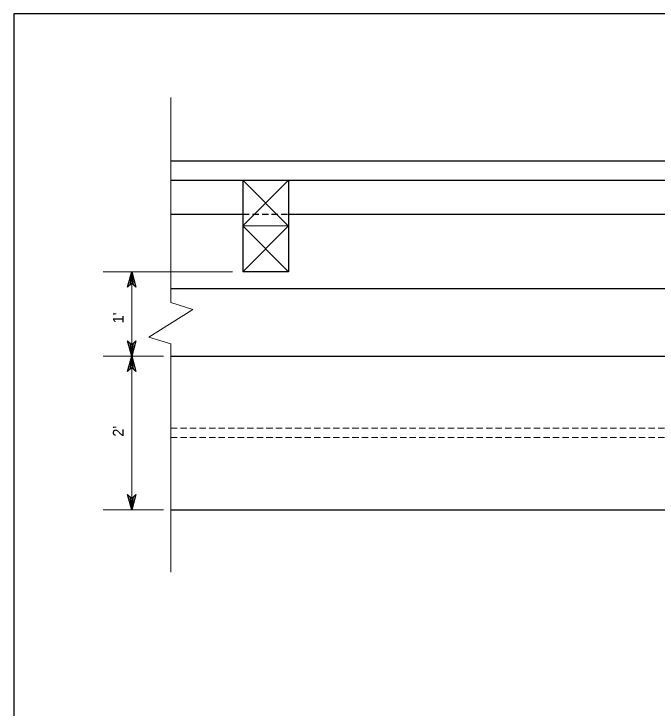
# Model space of a CAD drawing. Extents: x 993470 to 994006, y 1010815 to 1011161.
# Drawn here: x 993470 to 993630.6, y 1010988.2 to 1011161.5 of the extents above; entities that cross this region are included whole.
import ezdxf
from ezdxf.enums import TextEntityAlignment as Align

# ---------------------------------------------------------------- set-up
doc = ezdxf.new("R2010")
doc.units = 0
doc.header["$LTSCALE"] = 0.53
doc.linetypes.add('LONG_DASHED', pattern=[7.5, 6, -1.5])
doc.linetypes.add('MEDIUM_DASHED', pattern=[4.5, 3, -1.5])
for name, color, linetype, lineweight in [('1', 7, 'Continuous', 25), ('15', 7, 'Continuous', 13), ('16', 7, 'Continuous', 25), ('20', 7, 'Continuous', 13), ('30', 7, 'Continuous', 25), ('32', 7, 'Continuous', 25)]:
    doc.layers.add(name, color=color, linetype=linetype, lineweight=lineweight)

msp = doc.modelspace()

# ---------------------------------------------------------------- linework, layer by layer
at = {"layer": '1'}
for p, q in [((993527.157, 1011119.934), (993527.157, 1011097.116)), ((993538.559, 1011119.934), (993538.559, 1011097.116)), ((993509.149, 1011076.054), (993918.64, 1011076.054))]:
    msp.add_line(p, q, dxfattribs=at)
at = {"layer": '1', "linetype": 'MEDIUM_DASHED', "lineweight": 13}
for p, q in [((993509.149, 1011058.023), (993707.785, 1011058.023)), ((993509.149, 1011055.697), (993707.785, 1011055.697))]:
    msp.add_line(p, q, dxfattribs=at)
at = {"layer": '15'}
msp.add_lwpolyline([(993509.149, 1011079.129), (993503.685, 1011080.805), (993514.613, 1011087.717), (993509.149, 1011089.393)], dxfattribs=at)
at = {"layer": '16'}
for points in [[(993498.963, 1011093.876), (993498.335, 1011093.278), (993499.391, 1011097.116), (993500.447, 1011093.278), (993499.819, 1011093.876), (993499.391, 1011097.116), (993498.963, 1011093.876), (993499.391, 1011094.29), (993499.819, 1011093.876)], [(993499.819, 1011079.294), (993500.447, 1011079.894), (993499.391, 1011076.054), (993498.335, 1011079.894), (993498.963, 1011079.294), (993499.391, 1011076.054), (993499.819, 1011079.294), (993499.391, 1011078.88), (993498.963, 1011079.294)], [(993498.963, 1011072.816), (993498.335, 1011072.216), (993499.391, 1011076.054), (993500.447, 1011072.216), (993499.819, 1011072.816), (993499.391, 1011076.054), (993498.963, 1011072.816), (993499.391, 1011073.23), (993499.819, 1011072.816)], [(993499.819, 1011040.894), (993500.447, 1011041.494), (993499.391, 1011037.654), (993498.335, 1011041.494), (993498.963, 1011040.894), (993499.391, 1011037.654), (993499.819, 1011040.894), (993499.391, 1011040.48), (993498.963, 1011040.894)]]:
    msp.add_lwpolyline(points, dxfattribs=at)
at = {"layer": '30'}
for p, q in [((994005.609, 1011161.474), (993469.979, 1011161.474)), ((993469.979, 1011161.474), (993469.979, 1010814.89))]:
    msp.add_line(p, q, dxfattribs=at)
at = {"layer": '32', "lineweight": 13}
for p, q in [((993509.149, 1011089.393), (993509.149, 1011140.582)), ((993527.157, 1011119.934), (993538.559, 1011108.504)), ((993527.171, 1011108.532), (993538.559, 1011119.934)), ((993538.545, 1011108.532), (993527.157, 1011108.546)), ((993527.157, 1011108.546), (993538.559, 1011097.116)), ((993527.157, 1011097.116), (993538.545, 1011108.532)), ((993524.521, 1011097.116), (993492.264, 1011097.116)), ((993499.391, 1011097.116), (993499.391, 1011076.054)), ((993509.149, 1011022.09), (993509.149, 1011079.129)), ((993507.361, 1011076.054), (993492.264, 1011076.054)), ((993499.391, 1011037.654), (993499.391, 1011076.054)), ((993507.361, 1011037.654), (993492.264, 1011037.654))]:
    msp.add_line(p, q, dxfattribs=at)
at = {"layer": '32'}
for p, q in [((993509.149, 1011124.772), (993918.64, 1011124.772)), ((993509.149, 1011119.934), (993918.64, 1011119.934)), ((993509.149, 1011111.458), (993527.157, 1011111.458)), ((993538.559, 1011111.458), (993650.777, 1011111.458)), ((993538.559, 1011097.116), (993527.157, 1011097.116)), ((993509.149, 1011092.92), (993918.64, 1011092.92)), ((993509.149, 1011037.654), (993918.64, 1011037.654))]:
    msp.add_line(p, q, dxfattribs=at)
at = {"layer": '32', "linetype": 'LONG_DASHED', "lineweight": 13}
msp.add_line((993538.559, 1011119.934), (993527.157, 1011119.934), dxfattribs=at)
at = {"layer": '32', "linetype": 'MEDIUM_DASHED'}
msp.add_line((993527.157, 1011111.458), (993538.559, 1011111.458), dxfattribs=at)

# ---------------------------------------------------------------- texts
at = {"layer": '20'}
for s, p in [("1'", (993497.382, 1011085.5775)), ("2'", (993497.382, 1011057.2925))]:
    msp.add_text(s, height=2.697, rotation=90, dxfattribs=at).set_placement(p, align=Align.CENTER)

doc.saveas('drawing.dxf')
